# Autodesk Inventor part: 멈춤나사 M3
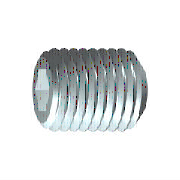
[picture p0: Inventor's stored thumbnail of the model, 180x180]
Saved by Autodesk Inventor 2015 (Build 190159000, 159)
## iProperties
IsCustomPart: 1
Created: 2012-02
Part Number: 멈춤나사 M3
Material: 강철, 연강
Description: 6각 소켓 머리 없는 멈춤 나사
Document SubType Name: Modeling
Standard: KS B 1028
Designer: mduedu
Standards Organization: KS
Language: ko-KR
Size Designation: 납작점M3x8
Categories: <MemberInstance><Categories><Category DisplayName="조임쇠" InternalName="e4da775c-781d-43d5-af7c-5136215cf5a6" Mnemonic="FSTN"><Category DisplayName="볼트" InternalN
Density: 1 g/cm^3
Appearance: 강철
Author: mduedu
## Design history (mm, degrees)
sketch "스케치1"
  geometry: L1 (0, 0)-(5.5, 0); L2 (8, 0.866)-(8, 1.5); L3 (8, 1.5)-(0, 1.5); L4 (8, 0.866)-(6, 0.866); L5 (6, 0.866)-(5.5, 0); L6 (0, -0.3)-(0, 1.8) reference; L7 (0, 1.5)-(0, 0)
  constraints: 13 end point, 3 parallel, 1 collinear, 1 perpendicular, 1 point on line
  dimensions: "d0" = 2 distance of L2.start L4.end (= INTI); "d1" = 60 deg angle of L5 L1; "d2" = 3 diameter of L3 L1 (= NND); "d3" = 1.73205 diameter of L4 L1 (= 1.1547 x SW); "d5" = 8 distance from line of L2 L3.end (= NLG)
revolve "본체" sketch "스케치1" stored, may be unused: angle "d6" = 90 deg
sketch "스케치2"
  geometry: L1 (-0.433, 0.75)-(0.433, 0.75); L2 (0.433, 0.75)-(0.866, 0); L3 (0.866, 0)-(0.433, -0.75); L4 (0.433, -0.75)-(-0.433, -0.75); L5 (-0.433, -0.75)-(-0.866, 0); L6 (-0.866, 0)-(-0.433, 0.75); A1 r 0.866 centre (0, 0) between (-0.433, 0.75) and (0.433, 0.75) reference; 2 further points
  constraints: 12 end point, 2 point on circle, 1 coincident, 1 horizontal, 11 other
extrude "슬롯" join sketch "스케치2" taper "d9" = 0 deg; stored distance "d21" = 10
workaxis "Work Axis1"
workplane "Work Plane1"
body "Solid1"
chamfer "모따기1" distance "d7" = 0.30673 (= -0.5 x GD1 + 0.5 x NND); stored, may be unused: angle "d8" = 45 deg (= FAWI), second distance "d29" = 0.30673 (= -0.5 x GD1 + 0.5 x NND)
feature "스레드" dims "d11" = 8 (= NLG), "d12" = 0
chamfer "모따기2" distance "d13" = 0.30673 (= -0.5 x GD1 + 0.5 x NND); stored, may be unused: angle "d14" = 45 deg (= FAWI), second distance "d30" = 0.30673 (= -0.5 x GD1 + 0.5 x NND)
other parameters: "NND" = 3 [user parameter; used in 5 equation terms], "NLG" = 8 [user parameter; used in 2 equation terms], "INTI" = 2 [user parameter; used in 1 equation term], "FAWI" = 45 deg [user parameter; used in 2 equation terms], "SW" = 1.5 [user parameter; used in 2 equation terms], "GD1" = 2.38655 (= THREADDIA - 1.2269 x PTC) [user parameter; used in 4 equation terms], "d4" = 0, "FAWI1" = 45 deg [user parameter], "d15" = 0, "d31" = 0, "GUL" = 0.30673 (= 0.61345 x PTC) [user parameter], "SPD" = 2 [user parameter], "TOA" = 30 deg [user parameter], "THREADDIA" = 3 [user parameter; used in 1 equation term], "PTC" = 0.5 [user parameter; used in 4 equation terms], "GAL" = 0.30673 (= 0.61345 x PTC) [user parameter], "E0" = 1.7325 (= 1.155 x SW) [user parameter]
